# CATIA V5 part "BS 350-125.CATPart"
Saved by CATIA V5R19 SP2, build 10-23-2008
Part number: BS 300-125
Bounding box of the stored display mesh (mm): x -15.868 to 15.868, y -15.868 to 15.868, z 0 to 280
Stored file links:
  C:\Users\Bora\Desktop\3D Katı model\BS serisi\BS 300\BS 300-125.CATPart
  C:\Program Files\Dassault Systemes\B19\intel_a\reffiles\standard\MetricThickPitch.txt
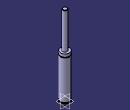
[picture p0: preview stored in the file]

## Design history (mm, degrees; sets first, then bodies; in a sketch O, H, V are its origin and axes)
Body1 (main body)
  Sketch1 on yz-plane, origin (0, 0, 0), H (0, 1, 0), V (0, 0, 1)
    point P1 (8, 279)
    point P3 (8, 279)
    point P5 (16, 144.5)
    point P6 (16, 142.5)
    point P9 (16, 144.5)
    point P14 (16, 142.5)
    line L1 (8, 279) -> (8, 154)
    arc A1 centre (7, 279) radius 1 from (8, 279) to (7, 280) ccw
    arc A2 centre (16, 143.5) radius 1 from (16, 144.5) to (16, 142.5) ccw
    line L2 (16, 0) -> (16, 4)
    line L3 (16, 144.5) -> (16, 154)
    line L4 (14.5, 7.5) -> (14.5, 4)
    line L5 (16, 7.5) -> (16, 142.5)
    line L6 (7, 280) -> (0, 280)
    point P15 (0, 280)
    line L7 (8, 154) -> (16, 154)
    line L8 (0, 0) -> (16, 0)
    line L9 (14.5, 7.5) -> (16, 7.5)
    line L10 (14.5, 4) -> (16, 4)
    coincidence: P15 V, P1 P3, P5 P9, P6 P14
    tangency: L6 A1
    horizontal: L7 H, L8 H, L9 H, L10 H
  Shaft1: profile Sketch1, axis Sketch1.V, angle 360
  Sketch2 on face of Shaft1 from Sketch1.L8, origin (0, 0, 0), H (1, 0, 0), V (0, -1, 0)
    point P1 (0, 0)
  Hole1: placed by Sketch2, at (0, 0, 0) direction (0, 0, 1), diameter 6.647, depth 4, threaded "M8", thread diameter 8, thread depth 4, pitch 1.25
